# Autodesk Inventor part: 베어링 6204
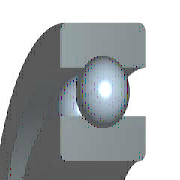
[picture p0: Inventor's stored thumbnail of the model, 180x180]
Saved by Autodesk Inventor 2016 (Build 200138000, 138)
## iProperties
Created: 2012-02
Part Number: 베어링 6204
Material: 강철, 연강
Description: 깊은 그루브 볼 베어링
Document SubType Name: Modeling
Standard: KS B 2023
Designer: mduedu
Standards Organization: KS
Language: ko-KR
Size Designation: 6204 - 20 x 47 x 14
Categories: <MemberInstance><Categories><Category DisplayName="샤프트 부품" InternalName="7f7aeb1f-a693-4053-b835-cee3144e0d98" Mnemonic="SHFT"><Category DisplayName="베어링" Inter
Density: 1 g/cm^3
Appearance: 노란색
IsCustomPart: 1
Author: mduedu
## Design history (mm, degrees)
sketch "스케치" dims "d0" = 7.02 (= -0.26 x WD + 0.26 x BD)
  geometry: L1 (3.49, 16.75)-(10.51, 16.75); L2 (7, 16.75)-(7, 13.24); L3 (7, 16.75)-(7, 20.26); L4 (4.392, 14.401)-(0, 14.401); L5 (0, 10)-(14, 10); L6 (4.392, 19.099)-(0, 19.099); L7 (0, 23.5)-(14, 23.5); L8 (14, 10)-(14, 14.401); L9 (9.608, 14.401)-(14, 14.401); L10 (9.608, 19.099)-(14, 19.099); L11 (14, 23.5)-(14, 19.099); L12 (-1.4, 0)-(8.4, 0) reference; L13 (0, -0.3)-(0, 5.3) reference
  constraints: 22 end point, 4 point on line, 2 collinear, 2 perpendicular, 2 symmetric about line, 1 midpoint, 1 parallel, 14 other
  dimensions: "d9" = 20 diameter of L5 L12 (= WD); "d11" = 47 diameter of L7 L12 (= BD); "d12" = 14 distance between parallel lines of L8 L13 (= KB); "d13" = 28.802 diameter of L9 L12 (= 0.326 x BD + 0.674 x WD)
revolve "본체" stored, may be unused: angle "d6" = 90 deg
revolve "볼" stored, may be unused: angle "d7" = 90 deg
pattern_circular "IDS_ARRAYBALL[SIMPL:T]" dims angle "d3" = 360 deg
body "Solid1"
fillet "모깎기1" dims "d1" = 1 (= KRS)
other parameters: "WD" = 20 [user parameter; used in 5 equation terms], "BD" = 47 [user parameter; used in 5 equation terms], "KB" = 14 [user parameter; used in 1 equation term], "KRS" = 1 [user parameter; used in 1 equation term], "d4" = 0, "d5" = 0, "d8" = 0, "d14" = 0, "d15" = 0, "BBA" = 0 [user parameter], "BC0" = 6550000 [user parameter], "BC" = 1.27e+07 [user parameter], "BR" = 23.5 (= 0.5 x BD) [user parameter]
